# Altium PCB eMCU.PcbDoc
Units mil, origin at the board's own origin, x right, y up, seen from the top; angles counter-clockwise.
Board outline 3031.5 x 2283.46 mil, 2 copper layers (Top Layer, Bottom Layer); 66 components, 80 nets, 347 pads, 50 vias.
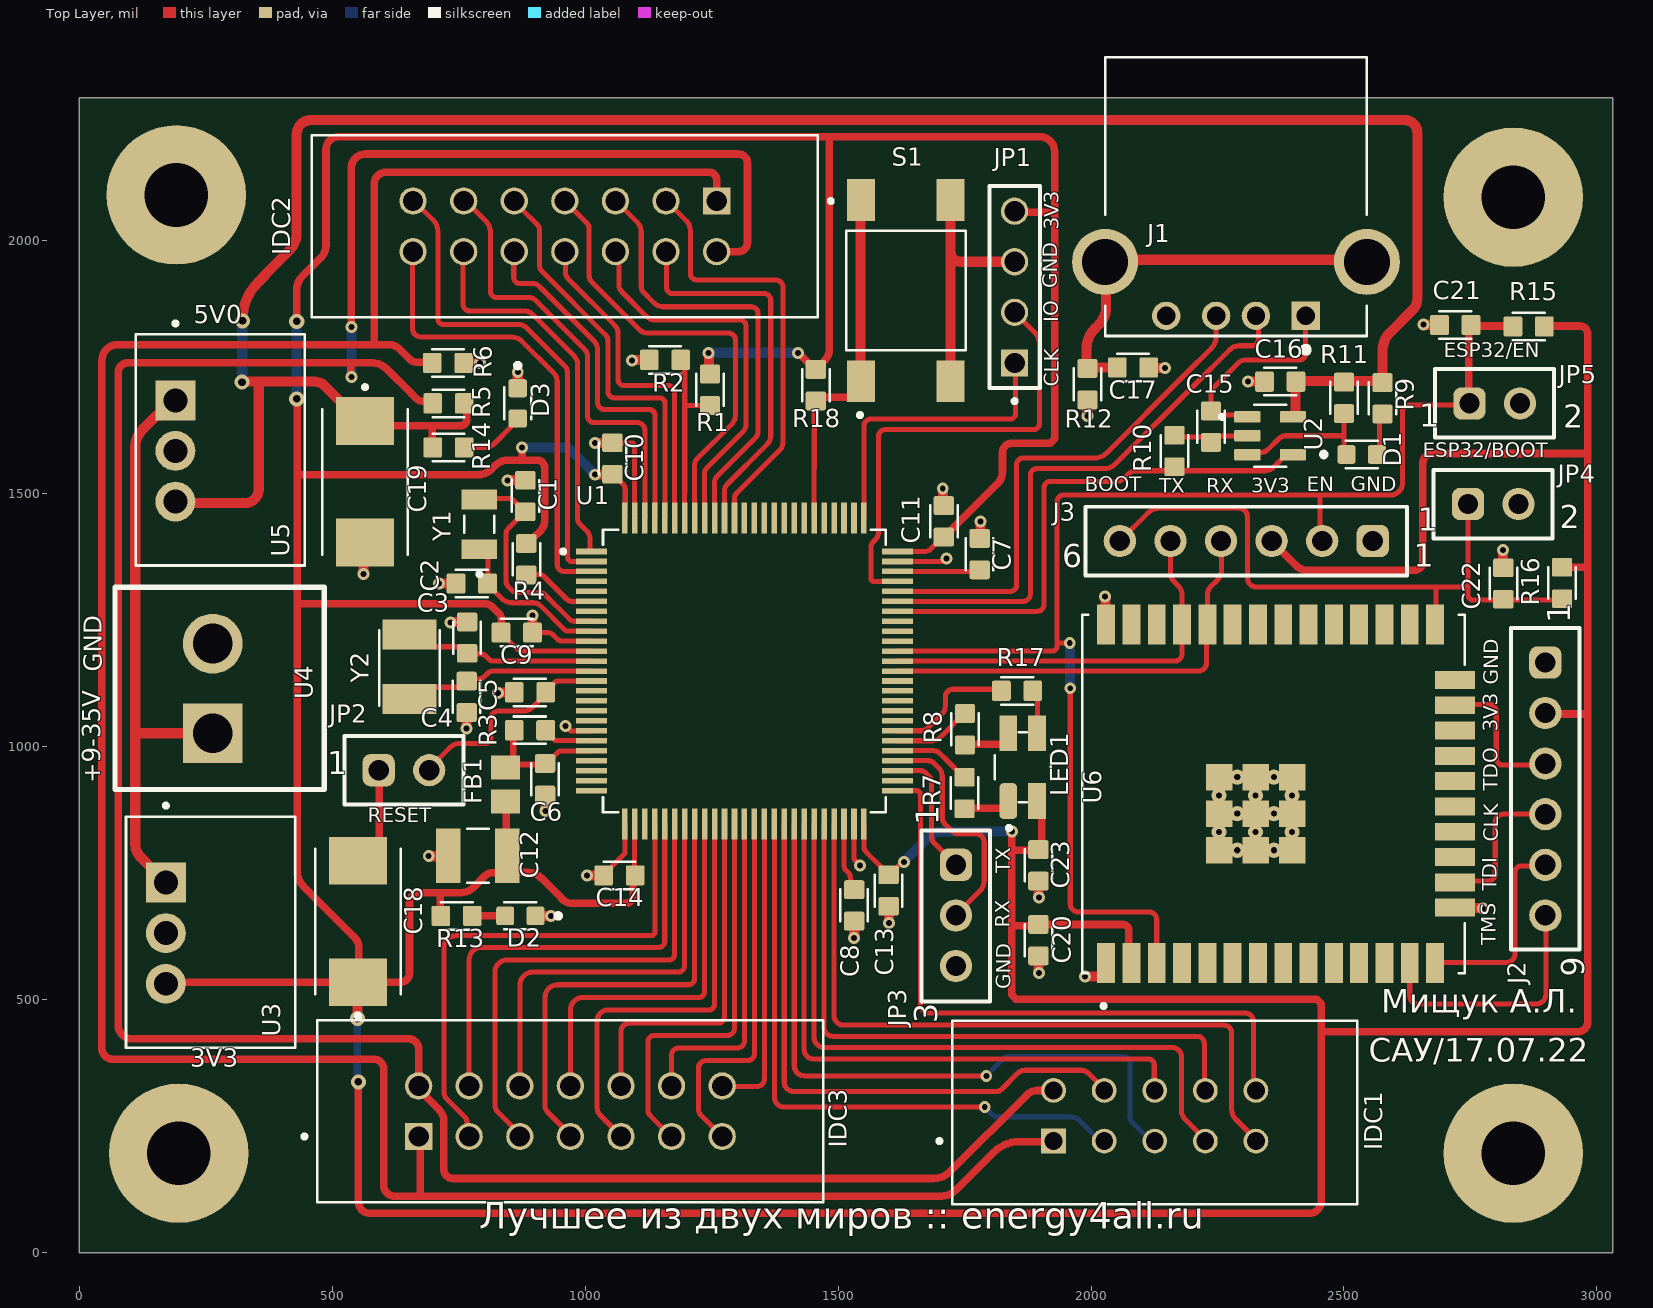
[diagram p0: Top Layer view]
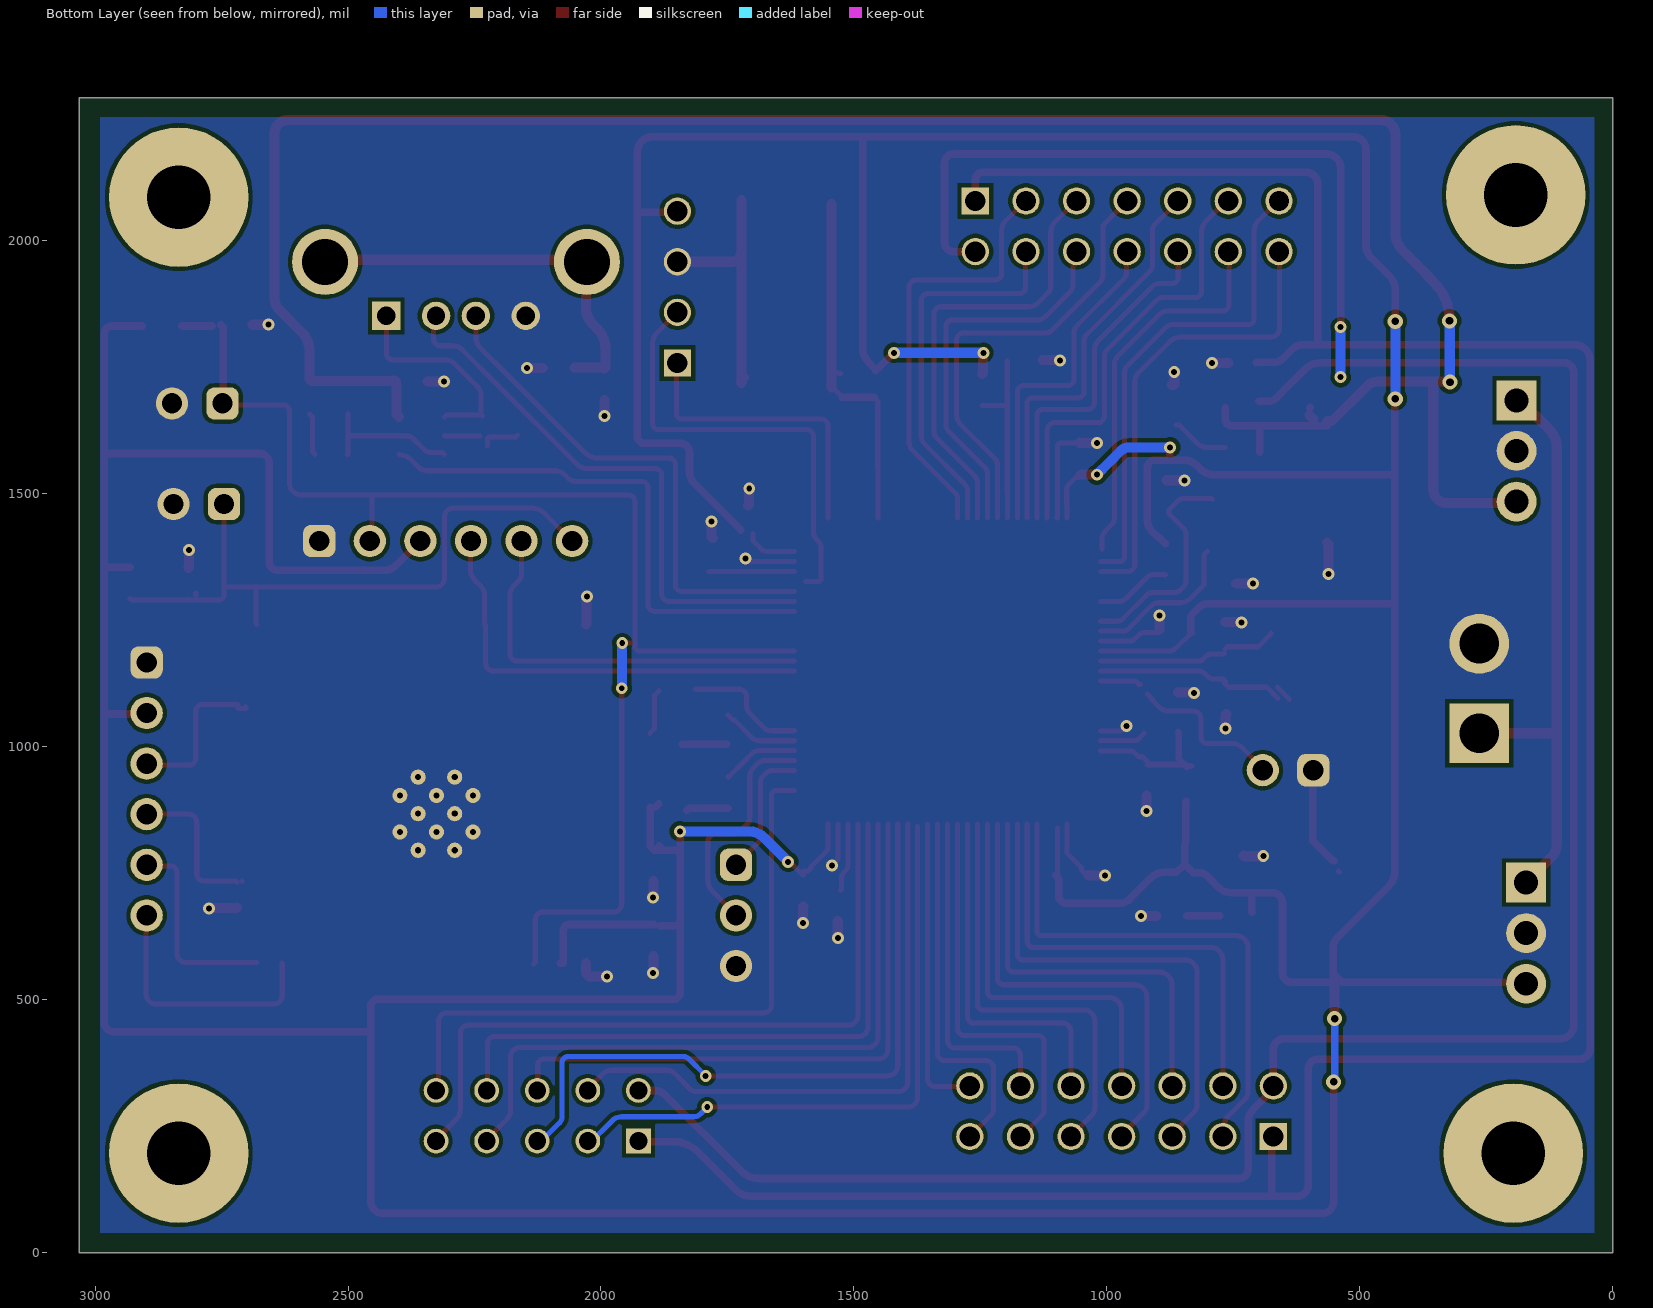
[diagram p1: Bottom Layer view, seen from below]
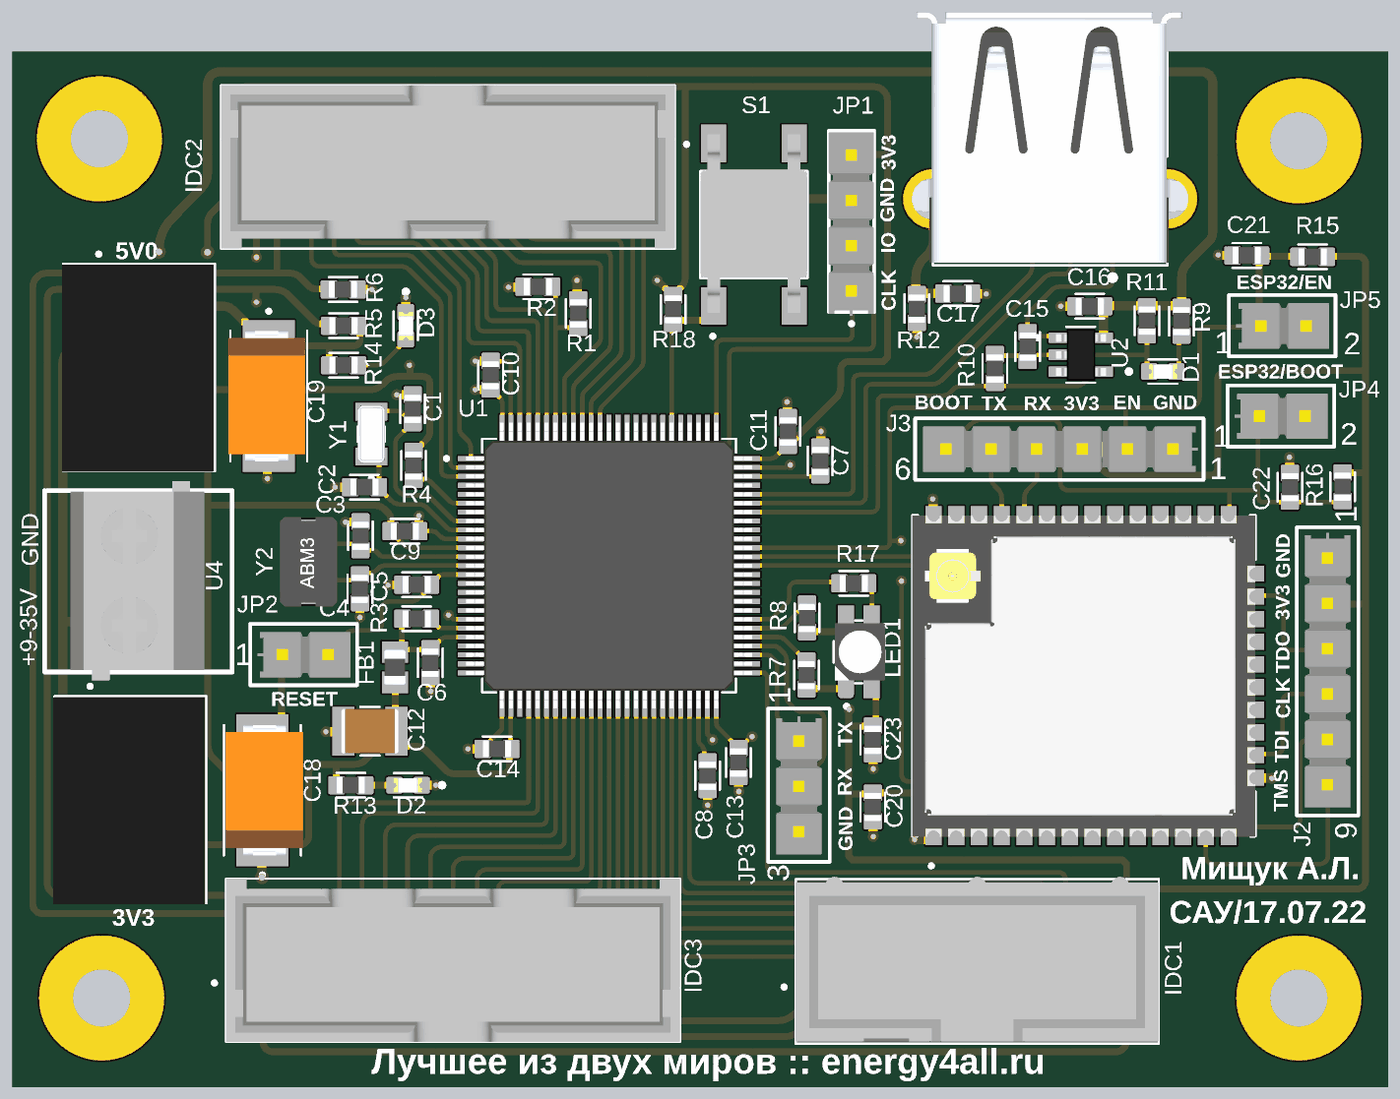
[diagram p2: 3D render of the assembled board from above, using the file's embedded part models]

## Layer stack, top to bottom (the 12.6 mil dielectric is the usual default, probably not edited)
Top Solder: solder mask 0.4, Solder Resist, Dk 3.5
Top Layer: signal copper 1.4
Dielectric 1: dielectric 12.6, FR-4, Dk 4.8
Bottom Layer: signal copper 1.4
Bottom Solder: solder mask 0.4, Solder Resist, Dk 3.5

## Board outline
0,0 3031.5,0 3031.5,2283.46 0,2283.46

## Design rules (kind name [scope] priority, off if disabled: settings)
Clearance [All] p1: gap=7.87 ignorepadtopadclearanceinfootprint=FALSE except(0: Arc-Hole Track-Hole SMDPad-Hole THPad-Hole Via-Hole Fill-Hole Poly-Hole Region-Hole Text-Hole)
HoleSize [All] p1: absolutevalues=TRUE maxlimit=200 minlimit=1 maxpercent=80.000 minpercent=20.000
MinimumSolderMaskSliver [All] p1 off: minsoldermaskwidth=10
PasteMaskExpansion [All] p1 off: expansion=0
PolygonConnect [All] p1: connectstyle=Direct reliefconductorwidth=10 reliefentries=4 polygonreliefangle="90 Angle" airgapwidth=10
RoomDefinition eConnect [InComponentClass('eConnect')] p1: confinementstyle=ConfineOut formatcopy=TRUE lockcomponents=FALSE outline 3083,747 3240,747 3240,817 3083,817
RoomDefinition eMCU [InComponentClass('eMCU')] p2: confinementstyle=ConfineOut formatcopy=TRUE lockcomponents=FALSE outline 3080,827 3240,827 3240,897 3080,897
RoomDefinition eWiFi [InComponentClass('eWiFi')] p3: confinementstyle=ConfineOut formatcopy=TRUE lockcomponents=FALSE outline 3084,520 3241,520 3241,588 3084,588
RoomDefinition eUSB [InComponentClass('eUSB')] p4: confinementstyle=ConfineOut formatcopy=TRUE lockcomponents=FALSE outline 3083,595 3241,595 3241,658 3083,658
RoomDefinition eSupply [InComponentClass('eSupply')] p5: confinementstyle=ConfineOut formatcopy=TRUE lockcomponents=FALSE outline 3082,668 3240,668 3240,738 3082,738
RoutingVias [All] p1: holewidth=28 width=50 viastyle="Through Hole" minholewidth=28 minwidth=50 maxholewidth=28 maxwidth=50
SilkToSilkClearance [All] p1 off: silktosilkclearance=5
SilkToSolderMaskClearance [IsPad] p1 off: minsilkscreentomaskgap=10 clearancetoexposedcopper=TRUE
SolderMaskExpansion [All] p1 off: expansion=4 istentingtop=FALSE
Width [All] p1: maxlimit=50 minlimit=10 preferedwidth=20
25 further rules are at their usual default settings.

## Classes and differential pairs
component class eWiFi: C20 C21 C22 J2 J3 JP4 JP5 R15 R16 U6
component class eUSB: C15 C16 C17 D1 J1 R9 R10 R11 R12 U2
component class eConnect: IDC2 IDC3 R5 R6
component class eSupply: C6 C7 C8 C9 C10 C11 C12 C13 C14 C18 C19 D2 D3 FB1 R3 R4 R13 R14 U3 U4 U5
component class eMCU: C1 C2 C3 C4 C5 C23 IDC1 JP1 JP2 JP3 LED1 R1 R2 R7 R8 R17 R18 S1 U1 Y Y1 Y2

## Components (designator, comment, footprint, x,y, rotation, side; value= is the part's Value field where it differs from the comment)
C1 "22pF" CAP_0603 882,1495.9 r270 top
C2 "22pF" CAP_0603 776,1323 r0 top
C3 "22pF" CAP_0603 767,1216 r270 top
C4 "22pF" CAP_0603 766,1099 r90 top
C5 "0.1uF" CAP_0603 891,1108 r0 top
C6 "0.1uF" CAP_0603 921,936 r90 top
C7 "4.7uF 25V" CAP_0603 1780,1381 r270 top
C8 "4.7uF 25V" CAP_0603 1532,686.9 r90 top
C9 "0.1uF" CAP_0603 865,1226 r180 top
C10 "0.1uF" CAP_0603 1054,1570 r270 top
C11 "0.1uF" CAP_0603 1709,1446 r270 top
C12 "47uF" CAP_1210 788,785 r0 top
C13 "0.1uF" CAP_0603 1600,716 r90 top
C14 "0.1uF" CAP_0603 1068,746 r0 top
C15 "0.1uF" CAP_0603 2237,1633 r270 top
C16 "0.1uF" CAP_0603 2374,1722 r180 top
C17 "0.01uF" CAP_0603 2083,1750 r180 top
C18 "100uF" CAP_TYPE_D 551,655 r90 top
C19 "100uF" CAP_TYPE_D 565,1524 r270 top
C20 "0.1uF" CAP_0603 1896,618 r90 top
C21 "0.1uF" CAP_0603 2720,1834 r0 top
C22 "0.1uF" CAP_0603 2815,1323 r270 top
C23 "0.1uF" CAP_0603 1896,766 r90 top
D1 "led_0603" led_0603 2535,1578 r0 top
D2 "led_0603" led_0603 872,666 r180 top
D3 "led_0603" led_0603 867,1679 r270 top
FB1 "LI0805H151R-10" LI0805H151R-10 843,926 r90 top
IDC1 "IDC-10" IDC-10 1926,221 r0 top
IDC2 "IDC-14" IDC-14 1260,2079 r0 top
IDC3 "IDC-14" IDC-14 671,230 r180 top
J1 "292303-1" TE_292303-1 2424.43,1852 r180 top
J2 "UART" TSW-106-07-F-S 2898,917 r270 top
J3 "UART" TSW-106-07-F-S 2307,1407 r180 top
JP1 "ST-LINK" TSW-104-07-F-S 1849,1759 r90 top
JP2 "RESET" TSW-102-07-F-S 642,954 r0 top
JP3 "TSW-103-07-F-S" TSW-103-07-F-S 1733,667 r270 top
JP4 "RESET" TSW-102-07-F-S 2795,1480 r0 top
JP5 "RESET" TSW-102-07-F-S 2798,1679 r0 top
LED1 "SX-3528-RGB-ANODE" SX-3528-RGB-ANODE 1865,960 r270 top
R1 "DNP" RESC1608X50N 1247,1706 r90 top
R2 "10k" RESC1608X50N 1158,1765 r0 top
R3 "1k" RESC1608X50N 890.9,1033 r0 top
R4 "1k" RESC1608X50N 884,1371 r270 top
R5 "0R" RESC1608X50N 730,1679 r180 top
R6 "0R" RESC1608X50N 729,1759 r180 top
R7 "10K" RESC1608X50N 1750,909 r270 top
R8 "10K" RESC1608X50N 1751,1035 r270 top
R9 "10k" RESC1608X50N 2576,1689 r90 top
R10 "10k" RESC1608X50N 2165,1585 r270 top
R11 "100k" RESC1608X50N 2500,1690 r90 top
R12 "1MOM" RESC1608X50N 1993,1717 r270 top
R13 "10K" RESC1608X50N 746,666 r180 top
R14 "10K" RESC1608X50N 730,1592 r180 top
R15 "10K" RESC1608X50N 2865,1831 r0 top
R16 "10K" RESC1608X50N 2931,1324 r90 top
R17 "10K" RESC1608X50N 1854,1111 r0 top
R18 "10K" RESC1608X50N 1456,1715 r90 top
S1 "2-1437565-8" 2-1437565-8 1634,1902 r90 top
U1 "STM32H750VBT6" STM32H750VBT6 1315,1150 r0 top
U2 "STMPS2151STR" STMPS2151STR 2354,1615 r0 top
U3 "R-78E5.0-1.0" R-78E5.0-1.0 260,632 r270 top
U4 "DG129-5.0-02P" DG129-5.0-02P 264,1115.58 r90 top
U5 "R-78E5.0-1.0" R-78E5.0-1.0 279,1585 r270 top
U6 "ESP32-WROOM-32U" ESP32-WROOM-32U 2361.07,907.37 r90 top
Y1 "32.768K" NX3215SA 791,1440 r90 top
Y2 "8MHZ" NX3225GD 653,1156 r90 top

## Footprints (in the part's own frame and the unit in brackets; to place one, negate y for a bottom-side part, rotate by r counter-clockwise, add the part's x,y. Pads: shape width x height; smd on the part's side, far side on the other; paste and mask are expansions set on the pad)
2-1437565-8 [mm]
  rect 2.1x1.4 smd: 1(-4.55,2.25) 2(4.55,2.25) 3(-4.55,-2.25) 4(4.55,-2.25)
  silkscreen extent -6.35,-3 3,3, body extent -4.95,-3 5.05,3, height 4.28
CAP_0603 [mm]
  rrect20% 0.94x1.02 smd: 1(-0.79,0) 2(0.79,0)
  silkscreen extent -0.8,-0.69 0.8,0.69, body extent -0.8,-0.47 0.8,0.48, height 0.78
CAP_1210 [mm]
  rect 1.24x2.73 smd: 1(-1.485,0) 2(1.485,0)
  silkscreen extent -0.54,-1.36 0.54,1.36, body extent -1.6,-1.25 1.6,1.25, height 1.97
CAP_TYPE_D [mm]
  rect 2.4x2.9 smd: 1(-3.05,0) 2(3.05,0)
  silkscreen extent -4.85,-2.15 3.65,2.15, body extent -3.65,-2.27 3.65,2.03, height 3.1
DG129-5.0-02P [mm]
  rect 3x3 hole 2: 1(-2.25,0)
  round 3 hole 2: 2(2.25,0)
  silkscreen extent -5.08,-5.6 5.08,4.9, body extent -5.55,-4.05 5.61,3.45, height 10.08
ESP32-WROOM-32U [mm]
  rect 2x0.9 smd: 1(-8.5,8.41) 2(-8.5,7.14) 3(-8.5,5.87) 4(-8.5,4.6) 5(-8.5,3.33) 6(-8.5,2.06) 7(-8.5,0.79) 8(-8.5,-0.48) 9(-8.5,-1.75) 10(-8.5,-3.02) 11(-8.5,-4.29) 12(-8.5,-5.56) 13(-8.5,-6.83) 14(-8.5,-8.1) 25(8.5,-8.1) 26(8.5,-6.83) 27(8.5,-5.56) 28(8.5,-4.29) 29(8.5,-3.02) 30(8.5,-1.75) 31(8.5,-0.48) 32(8.5,0.79) 33(8.5,2.06) 34(8.5,3.33) 35(8.5,4.6) 36(8.5,5.87) 37(8.5,7.14) 38(8.5,8.41)
  rect 0.9x2 smd: 15(-5.715,-9.1) 16(-4.445,-9.1) 17(-3.175,-9.1) 18(-1.905,-9.1) 19(-0.635,-9.1) 20(0.635,-9.1) 21(1.905,-9.1) 22(3.175,-9.1) 23(4.445,-9.1) 24(5.715,-9.1)
  rect 1.33x1.33 smd: G.1(0.835,2.745) G.2(-1,2.745) G.4(-2.835,2.745) G.5(0.835,0.91) G.6(-1,0.91) G.7(-2.835,0.91) G.8(0.835,-0.925) G.9(-1,-0.925) G.10(-2.835,-0.925)
  round 0.762 hole 0.305: G.11(-0.082,2.745) G.12(-1.917,2.745) G.13(0.835,1.827) G.14(-1,1.827) G.15(-2.835,1.827) G.16(-0.082,0.91) G.17(-1.917,0.91) G.18(0.835,-0.008) G.19(-1,-0.008) G.20(-2.835,-0.008) G.21(-0.082,-0.925) G.22(-1.917,-0.925)
  silkscreen extent -10.75,-9.6 9,9.6, body extent -9.02,-9.6 8.98,9.6, height 3.3
IDC-10 [mm]
  rect 1.24x1.24 hole 0.89: 1(0,0)
  round 1.24 hole 0.89: 2(0,2.54) 3(2.54,0) 4(2.54,2.54) 5(5.08,0) 6(5.08,2.54) 7(7.62,0) 8(7.62,2.54) 9(10.16,0) 10(10.16,2.54)
  silkscreen extent -5.83,-3.17 15.24,6.04, body extent -5.08,-3.05 15.24,6.17, height 8.89
IDC-14 [mm]
  rect 1.37x1.37 hole 1.02: 1(0,0)
  round 1.37 hole 1.02: 2(0,-2.54) 3(-2.54,0) 4(-2.54,-2.54) 5(-5.08,0) 6(-5.08,-2.54) 7(-7.62,0) 8(-7.62,-2.54) 9(-10.16,0) 10(-10.16,-2.54) 11(-12.7,0) 12(-12.7,-2.54) 13(-15.24,0) 14(-15.24,-2.54)
  silkscreen extent -20.32,-5.84 5.83,3.3, body extent -20.32,-5.84 5.08,3.3, height 9.25
led_0603 [mm]
  rrect25% 0.91x0.93 smd: A(0.76,0) C(-0.76,0)
  silkscreen extent -2.02,-0.68 0.8,0.68, body extent -0.78,-0.4 0.82,0.4, height 0.65
LI0805H151R-10 [mm]
  rect 1.2x1.45 smd: 1(-0.85,0) 2(0.85,0)
  body extent -1,-0.62 1,0.63, height 1.15
NX3215SA [mm]
  rect 1x1.8 smd: 1(-1.25,0) 2(1.25,0)
  silkscreen extent -2.6,-0.75 0.43,0.75, body extent -1.6,-0.75 1.6,0.75, height 0.9
NX3225GD [mm]
  rect 1.5x2.7 smd: 1(-1.552,0.007) 2(1.686,0.002)
  silkscreen extent -1.91,-1.52 1.91,1.52, body extent -2.43,-1.59 2.57,1.61, height 1.3
R-78E5.0-1.0 [mm]
  rect 2x2 hole 1.2: 1(-2.54,-2.25)
  round 2 hole 1.2: 2(0,-2.25) 3(2.54,-2.25)
  silkscreen extent -6.5,-4.25 5.75,4.25, body extent -5.8,-4.31 5.8,4.19, height 10.41
RESC1608X50N [mm]
  rrect20% 0.94x1.02 smd: 1(-0.79,0) 2(0.79,0)
  silkscreen extent -0.8,-0.69 0.8,0.69, body extent -0.79,-0.48 0.81,0.47, height 0.78
STM32H750VBT6 [mm]
  rrect7% 1.56x0.28 smd: 1(-7.68,6) 2(-7.68,5.5) 3(-7.68,5) 4(-7.68,4.5) 5(-7.68,4) 6(-7.68,3.5) 7(-7.68,3) 8(-7.68,2.5) 9(-7.68,2) 10(-7.68,1.5) 11(-7.68,1) 12(-7.68,0.5) 13(-7.68,0) 14(-7.68,-0.5) 15(-7.68,-1) 16(-7.68,-1.5) 17(-7.68,-2) 18(-7.68,-2.5) 19(-7.68,-3) 20(-7.68,-3.5) 21(-7.68,-4) 22(-7.68,-4.5) 23(-7.68,-5) 24(-7.68,-5.5) 25(-7.68,-6) 51(7.68,-6) 52(7.68,-5.5) 53(7.68,-5) 54(7.68,-4.5) 55(7.68,-4) 56(7.68,-3.5) 57(7.68,-3) 58(7.68,-2.5) 59(7.68,-2) 60(7.68,-1.5) 61(7.68,-1) 62(7.68,-0.5) 63(7.68,0) 64(7.68,0.5) 65(7.68,1) 66(7.68,1.5) 67(7.68,2) 68(7.68,2.5) 69(7.68,3) 70(7.68,3.5) 71(7.68,4) 72(7.68,4.5) 73(7.68,5) 74(7.68,5.5) 75(7.68,6)
  rrect7% 0.28x1.56 smd: 26(-6,-7.68) 27(-5.5,-7.68) 28(-5,-7.68) 29(-4.5,-7.68) 30(-4,-7.68) 31(-3.5,-7.68) 32(-3,-7.68) 33(-2.5,-7.68) 34(-2,-7.68) 35(-1.5,-7.68) 36(-1,-7.68) 37(-0.5,-7.68) 38(0,-7.68) 39(0.5,-7.68) 40(1,-7.68) 41(1.5,-7.68) 42(2,-7.68) 43(2.5,-7.68) 44(3,-7.68) 45(3.5,-7.68) 46(4,-7.68) 47(4.5,-7.68) 48(5,-7.68) 49(5.5,-7.68) 50(6,-7.68) 76(6,7.68) 77(5.5,7.68) 78(5,7.68) 79(4.5,7.68) 80(4,7.68) 81(3.5,7.68) 82(3,7.68) 83(2.5,7.68) 84(2,7.68) 85(1.5,7.68) 86(1,7.68) 87(0.5,7.68) 88(0,7.68) 89(-0.5,7.68) 90(-1,7.68) 91(-1.5,7.68) 92(-2,7.68) 93(-2.5,7.68) 94(-3,7.68) 95(-3.5,7.68) 96(-4,7.68) 97(-4.5,7.68) 98(-5,7.68) 99(-5.5,7.68) 100(-6,7.68)
  silkscreen extent -9.2,-7.1 7.1,7.1, body extent -8,-8 8,8, height 1.49
STMPS2151STR [mm]
  rrect25% 1.32x0.59 smd: 1(-1.145,0.95) 2(-1.145,0) 3(-1.145,-0.95) 4(1.145,-0.95) 5(1.145,0.95)
  silkscreen extent -2.51,-1.57 0.8,1.57, body extent -1.38,-1.46 1.42,1.44, height 1.15
SX-3528-RGB-ANODE [mm]
  rrect50% 1.8x0.9 smd: 1(1.7,-0.725)
  rect 1.8x0.9 smd: 2(-1.7,-0.725) 3(-1.7,0.725) 4(1.7,0.725)
  silkscreen extent -1.75,-1.4 3.15,1.4, body extent -1.75,-1.32 1.75,1.48, height 0.8
TE_292303-1 [mm]
  rect 1.428x1.428 hole 0.92: 1(0,0)
  round 1.428 hole 0.92: 2(2.5,0) 3(4.5,0) 4(7,0)
  round 3.316 hole 2.3: SH1(-3.07,-2.71) SH2(10.07,-2.71)
  silkscreen extent -3.07,-12.99 10.06,1.85, body extent -4.44,-13.15 11.56,0.85, height 7.78
TSW-102-07-F-S [mm]
  rrect50% 1.62x1.62 hole 1.02: 1(-1.27,0)
  round 1.62 hole 1.02: 2(1.27,0)
  silkscreen extent -2.99,-1.72 2.98,1.72, body extent -2.58,-1.28 2.62,1.26, height 8.38
TSW-103-07-F-S [mm]
  rrect50% 1.62x1.62 hole 1.02: 1(-2.54,0)
  round 1.62 hole 1.02: 2(0,0) 3(2.54,0)
  silkscreen extent -4.26,-1.72 4.32,1.72, body extent -3.85,-1.27 3.9,1.27, height 8.38
TSW-104-07-F-S [mm]
  rect 1.37x1.37 hole 1.02: 1(0,0)
  round 1.37 hole 1.02: 2(2.54,0) 3(5.08,0) 4(7.62,0)
  silkscreen extent -2.02,-1.27 8.89,1.27, body extent -1.49,-1.25 8.8,1.29, height 9.27
TSW-106-07-F-S [mm]
  rrect50% 1.62x1.62 hole 1.02: 1(-6.35,0)
  round 1.62 hole 1.02: 2(-3.81,0) 3(-1.27,0) 4(1.27,0) 5(3.81,0) 6(6.35,0)
  silkscreen extent -8.07,-1.72 8.07,1.72, body extent -7.75,-1.27 7.62,1.27, height 8.38

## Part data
C1 C2 C3 C4 C5 C6 C7 C8 C9 C10 C11 C13 C14 C15 C16 C17 C20 C21 C22 C23: library part CAP_0603
C12: library part CAP_1210
C18 C19: library part CAP_TYPE_D, Package=None
D1 D2 D3: "LED Indication - Discrete 3.1V 0603 _1608 Metric_", Package="0603 Lite-On"
FB1: "150 Ohms @ 100MHz 1 Power, Signal Line Ferrite Bead 0805 (2012 Metric) 800mA 150mOhm", Package="0805 Laird"
IDC1: "Header, Pin, Idc, Amp-Latch, 10 Pos, Low Profile, Pcb, Vertical, Blue", Package=None
IDC2 IDC3: "HEADER, PIN, AMP-LATCH, 14 POS, 2.54 X 2.54, VERTICAL, LOW PROFILE, PCB", Package=None
J1: "Conn; Data; USB; Recept; 2.0; 4 Pos; 1 Port; Rt Angle; A Ser; Tin over Copper", Package=None
J2 J3: library part TSW-106-07-F-S
JP1: library part TSW-104-07-F-S, "Connector Header Through Hole 4 position 0.100 (2.54mm)", Package=None
JP2 JP4 JP5: library part TSW-102-07-F-S
LED1: "LED; SMD 3528, PLCC2; RGB; 3.5x2.8mm; 120Â°; RGB;   3.2-3.6V", Package="PLCC-2 Lucky Light"
R1 R2 R3 R4 R5 R6 R7 R8 R9 R10 R11 R12 R13 R14 R15 R16 R17 R18: library part RES_0603, "1% 0.1W", Package=None
S1: Package=None
U1: "ARM Cortex-M7 STM32H7 Microcontroller IC 32-Bit 480MHz 128KB _128K x 8_ FLASH 100-LQFP _14x14_", Package="LQFP-100 STMicroelectronics"
U2: library part STMPS2141STR, "Power Switch/Driver 1:1 N-Channel 500mA SOT-23-5", Package="SOT-23 STMicroelectronics"
U3 U5: "1A DC/DC-Converter SIP3", Package="SIP-3 Recom Power"
U4: "DG129-5.0-02P-14-00A(H)"
U6: "Bluetooth, WiFi 802.11b/g/n, Bluetooth v4.2 +EDR, Class 1, 2 and 3 Transceiver Module 2.4GHz ~ 2.5GHz Antenna Not Included, U.FL Surface Mount", Package="Module Espressif Systems"
Y1: library part NX3215SA-32.768K-STD-MUA-8, "32.768 kHz Â±20ppm Crystal 12.5pF 70 kOhms 2-SMD, No Lead", Package="SMD-2 NDK"
Y2: library part NX3225GD, "8MHz Â±20ppm Crystal 18pF 140 Ohms 2-SMD, No Lead", Package="SMD-2 Abracon"

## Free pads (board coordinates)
  round 275.59 hole 125.98: 1(196.85,196.85) 2(192,2091) 3(2834.65,2086.61) 4(2834.65,196.85)

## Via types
v1: diameter 23.62, hole 11.81, Top Layer to Bottom Layer, tented both sides, 44 vias
v2: diameter 30, hole 15, Top Layer to Bottom Layer, tented both sides, 6 vias

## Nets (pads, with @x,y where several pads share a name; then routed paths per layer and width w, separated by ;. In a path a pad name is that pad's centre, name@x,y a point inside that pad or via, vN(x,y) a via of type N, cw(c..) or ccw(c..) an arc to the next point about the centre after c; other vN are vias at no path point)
3V3: C9.2 C10.2 C11.2 C12.2 C13.2 C14.2 C18.1 C20.2 C23.2 FB1.1 J2.2 J3.3 JP1.4 LED1.4 R1.2 R4.1 R13.2 R15.2 R16.2 R18.2 U1.11 U1.27 U1.50 U1.75 U1.100 U3.3 U6.2 | length 15550.6
  Top Layer w10: C9.2 833.9,1224.43 847.4,1210.92 848.08,1210.92 863.77,1195.23 ; 863.78,1195.22 ccw(c877.28,1208.74) 877.28,1189.64 ; 877.28,1189.57 1012.44,1189.57 U1.11 ; C10.2@1057,1533 1061.47,1533 1074.74,1519.74 ; 1074.75,1519.72 cw(c1063.4,1508.4) 1079.42,1509.03 ; U1.100 1078.78,1477.56 1079.42,1478.2 1079.42,1509.03 ; 1079.43,1508.4 ccw(c1063.4,1508.4) 1079.42,1509.03 ; C14.2@1098,740 U1.27@1098,840 ; R1.2@1246.82,1737.29 R1.2 ; U1.50 1551,847.42 1551,804.07 ccw(c1568.07,804.07) 1556,792 1584.92,763.08 1584.92,760.61 1590.43,755.1 C13.2@1600,755.1 ; C13.2 1601.57,747.1 1627.47,773 v1(1630,773) ; U1.75 1617.58,1386 1670,1386 ccw(c1670,1405.31) 1683.66,1391.66 1693.39,1401.39 1693.92,1401.39 1700,1407.47 C11.2@1700,1422 ; JP1.4@1827,2050 JP1.4@1827,2057
  Top Layer w15: U3.3 174.42,535 535.08,535 C18.1@547,546.92 ; v2(430,1688) 431,1687 431,1283 431,754.38 ccw(c472.97,754.38) 443.29,724.71 529.15,638.85 543.1,624.9 cw(c519.2,601) 553,601 553,546.92 551,544.92 C18.1 634.92,534.92 ccw(c634.92,553) 653,553 653,692 cw(c673,692) 673,712 714,712 ; v2(430,1841) 430,1903.44 cw(c467.56,1903.44) 440.97,1929.97 ; 434,1283 800,1283 cw(c800,1256.44) 818.78,1275.22 829.77,1264.23 cw(c819.51,1254) 834,1254 834,1226.1 C9.2 ; 436.29,1538 788.44,1538 ccw(c788.44,1575.56) 814.97,1548.97 ; 441,1930 478,1967 ccw(c453.86,1991.14) 488,1991.14 488,2181 cw(c513,2181) 513,2206 1899,2206 cw(c1899,2177) 1928,2177 1928,1608.79 1919.21,1600 1843,1600 ccw(c1843,1582) 1825,1582 1825,1544.14 cw(c1790.86,1544.14) 1815.02,1520.02 1724.08,1429.08 1724.08,1428.4 C11.2@1723.68,1428 ; C18.1@549,532.92 C18.1@550,531.92 ; v2(552,338) 552,101 ccw(c575,101) 575,78 2431,78 ccw(c2431,102) 2455,102 2455,437 ; R13.2@713,673 ccw(c710.59,675.41) 714,675.41 714,712 ; 815,1549 822.39,1556.39 cw(c848,1530.79) 848,1567 876,1567 ; FB1.1 844,891.54 C12.2@844,811.8 ; C12.2@846.46,806 C12.2 C12.2@846.46,768.25 ; v1(875,1592) 876,1591 876,1567 ; R4.1@885,1402 896.11,1413.11 897.68,1413.11 913.29,1428.71 ; 913,1429 ccw(c896.1,1445.9) 920,1445.9 920,1552 ccw(c905,1552) 905,1567 876,1567 ; C14.2@1096.1,740 1095,738.9 1095,705 cw(c1081,705) 1093,697.78 1088.22,693 cw(c1081,705) 1081,691 975.02,691 cw(c975.02,720.02) 954.51,699.49 912,742 ccw(c887.86,717.86) 887.86,752 862.72,752 C12.2@846.46,768.25 ; C14.2 C14.2@1101,746 ; v1(1421,1779) 1421.53,1779 R18.2@1457,1743.53 ; R18.2 1457.57,1746.1 1468.58,1757.11 1468.58,1758.68 1473.95,1764.05 ccw(c1452.1,1785.9) 1483,1785.9 1483,2203 ; v1(1844,833) 1843,832 1843,792.32 ; JP1.4@1875.68,2057 1927.14,2057 ; C23.2@1883,803.1 C23.2@1884.54,804.65 ; C20.2@1883.85,646.65 1883.61,646.9 1843,646.9 ; LED1.4@1885.54,888.07 LED1.4@1893,880.61 ; C20.2 2062.9,649.1 cw(c2062.9,637) 2066.89,648.42 cw(c2062.9,637) 2074.32,640.99 cw(c2062.9,637) 2075,637 2075,572.72 U6.2 ; LED1.4@1903,880.61 1903,804.1 C23.2 1894.9,796 1846.68,796 1843,792.32 ; J3.3 2405.1,1358.9 ccw(c2429,1382.8) 2429,1349 2639,1349 ccw(c2639,1366) 2656,1366 2656,1561 cw(c2675,1561) 2675,1580 2982,1580 ; J2.2 2900,1065 2982,1065 ; R15.2@2906.34,1832 2966,1832 cw(c2966,1816) 2982,1816 2982,1580 ; R16.2 2931.1,1355 2982,1355 ; 714,712 754.86,712 ccw(c754.86,746.14) 778.98,721.98 802.22,745.22 cw(c817,730.44) 817,751.34 829.56,751.34 C12.2@846.46,768.25 ; 1843,646.9 1843,509.79 1851.79,501 2446.21,501 2455,492.21 2455,437 ; 1843,646.9 1843,792.32 ; 2455,437 2962,437 ccw(c2962,457) 2982,457 2982,1065 ; 2982,1065 2982,1355 ; 2982,1355 2982,1580
  Top Layer w20: v2(550,463) C18.1@550,531.92 ; v1(1020,1538) 1020.45,1538.45 C10.2@1051.55,1538.45 ; v1(1244,1779) 1244.69,1778.31 1244.69,1739.41 R1.2@1246.82,1737.29
  Bottom Layer w15: v2(550,463) 550,340 v2(552,338)
  Bottom Layer w20: v2(430,1688) v2(430,1841) ; v1(875,1592) 956.1,1592 cw(c956.1,1568.1) 973,1585 994.68,1563.32 994.75,1563.32 1020,1538.07 v1(1020,1538) ; v1(1244,1779) v1(1421,1779) ; v1(1630,773) 1677.45,820.45 cw(c1707.83,790.07) 1706.17,833 ; 1707.83,833.03 ccw(c1707.83,790.07) 1706.17,833 ; v1(1844,833) 1706.17,833
5V: C16.1 C19.1 R5.1 R9.2 R11.2 R14.2 U2.5 U5.3 | length 4487.1
  Top Layer w15: C19.1@565,1635 754,1635 ccw(c754,1647) 766,1647 R5.1@766,1670 ; C19.1@598,1671 C19.1@599.1,1669.9 ; R14.2@698,1583 698,1633
  Top Layer w20: U5.3@188,1482 328,1482 ccw(c328,1509) 355,1509 355,1718.59 ccw(c351.59,1718.59) 354,1721 ; v2(323,1842) 323,1845.58 cw(c423,1845.58) 352.29,1916.29 358.22,1922.22 ; v2@333,1722 465.69,1722 cw(c465.69,1694.69) 485,1714 ; 366,1930 358.22,1922.22 ; 415.86,1981.86 369.92,1935.92 369.85,1935.85 ccw(c450.08,1855.62) 358.22,1922.22 ; 415.88,1981.88 ccw(c381.72,2016) 430,2016 430,2211 cw(c458,2211) 435.87,2228.15 cw(c458,2211) 440.85,2233.13 cw(c458,2211) 458,2239 2620,2239 cw(c2620,2214) 2645,2214 2645,1885.73 cw(c2614.27,1885.73) 2636.02,1864.02 2590.29,1818.29 ; 485.12,1714.12 555.16,1644.08 C19.1 ; C19.1@592,1648 C19.1@600,1656 ; U2.5 2403.92,1657.25 C16.1@2403.92,1714.92 ; C16.1 2406.1,1723 C16.1@2408.55,1723 ; C16.1@2409.84,1724.29 C16.1@2408.55,1723 ; 2590.27,1818.27 ccw(c2623.58,1785) 2576.5,1785 2576.5,1727.5 2572,1723 C16.1@2408.55,1723
  Bottom Layer w20: v2(322,1721) 322.5,1721.5 322.5,1841.5 v2(323,1842)
5V_GND: C15.2 R10.1 U2.2 | length 146.6
  Top Layer w10: R10.1 2168.1,1613 2221.92,1613 2224,1610.92 C15.2@2224,1595 ; C15.2@2239.7,1614.23 2308.15,1614.23 U2.2
GND: C1.1 C2.1 C3.1 C4.1 C5.1 C6.1 C7.1 C8.1 C9.1 C10.1 C11.1 C12.1 C13.1 C14.1 C16.2 C17.1 C18.2 C19.2 C20.1 C21.1 C22.1 C23.1 D2.C D3.C J1.4 J2.1 J3.1 JP1.3 JP2.1 JP3.3 JP4.2 JP5.2 R2.1 R6.1 R12.2 S1.3 S1.4 U1.10 U1.19 U1.26 U1.49 U1.74 U1.99 U3.2 U4.2 U5.2 U6.1 U6.15 U6.38 U6.G.1 U6.G.2 U6.G.4 U6.G.5 U6.G.6 U6.G.7 U6.G.8 U6.G.9 U6.G.10 U6.G.11 U6.G.12 U6.G.13 U6.G.14 U6.G.15 U6.G.16 U6.G.17 U6.G.18 U6.G.19 U6.G.20 U6.G.21 U6.G.22 | length 2432.1
  Top Layer w10: C18.2@540.56,752.82 C18.2@542,754.25 ; C9.1 925,1226 cw(c925,1209.1) 936.94,1221.06 944,1214 ccw(c955.94,1225.94) 955.94,1209.06 U1.10 ; C6.1 C6.1@922,903.9 ; v1(961,1041) 962.04,1041 971.15,1031.89 U1.19 ; C14.1 C14.1@1036.9,747 ; C14.1@1038.4,744.5 1050.4,756.5 1050.4,761.4 1078.78,789.78 U1.26 ; C10.1@1059.32,1600.63 1091.37,1600.63 cw(c1091.37,1594) 1092.19,1600.58 cw(c1091.37,1594) 1097.95,1594.82 cw(c1091.37,1594) 1098,1594 1098,1452.83 U1.99 ; U1.49 1531.54,778.67 1543,767.2 v1(1543,766) ; U1.74 1704.85,1366.54 1710.31,1372 v1(1714,1372) ; C7.1@1779,1413.1 C7.1 ; C17.1 C17.1@2115.1,1749 ; C16.2@2339.79,1722 C16.2@2342.9,1725.11 ; C16.2 C16.2@2344,1722 ; J2.1@2898,1177 J2.1@2900.48,1174.52
  Top Layer w15: C18.2 553.26,775.08 593,814.82 JP2.1@593,937.82
  Top Layer w20: v1(562,1342) 562,1400.92 C19.2 ; v1(691,784) 728.54,784 C12.1 ; v1(711,1323) C2.1 ; v1(734,1246) 734.55,1246.55 766.45,1246.55 C3.1 ; R6.1 v1(792,1759) ; C4.1@764,1064.9 766,1062.9 v1(766,1036) ; v1(828,1107) 828.5,1107.5 859.4,1107.5 C5.1 ; v1(847,1527) C1.1 ; v1(867,1741) 867,1716.83 868.11,1715.72 D3.C@872.26,1715.72 ; v1(896,1260) 896.05,1259.95 896.05,1232.05 C9.1@896.1,1232 ; D2.C v1(933,666) ; v1(922,873) 921.5,873.5 921.5,903.4 C6.1@922,903.9 ; v1(1004,746) 1035.9,746 C14.1@1036.9,747 ; v1(1020,1601) 1020.05,1601.05 1053.95,1601.05 C10.1 ; v1(1093.18,1764) 1093.68,1764.5 1126.4,1764.5 R2.1 ; v1(1532,622) C8.1 ; C13.1 1600.5,684.4 1600.5,652.5 v1(1601,652) ; v1(1707,1511) 1707.69,1510.31 1707.69,1478.41 C11.1 ; S1.3@1717,1730 ccw(c1717,1735.58) S1.3@1722.58,1735.58 ; S1.4 1722.58,1977.42 ; S1.3@1723,1719 cw(c1724.01,1720.01) 1722.58,1720.01 S1.3 1722.58,1977.42 ; C7.1@1779,1413.1 1779.1,1413 1781.31,1415.2 1781.31,1445.31 v1(1782,1446) ; JP1.3 1741,1959 cw(c1741,1977.42) 1722.58,1977.42 ; C20.1 1896.5,586.4 1896.5,553.5 v1(1897,553) ; C23.1 1896.5,734.4 1896.5,702.5 v1(1897,702) ; v1(1988,546) 2022.25,546 2029.97,553.72 U6.1 ; v1(1993,1654) R12.2 ; v1(2028,1297) 2028.69,1296.31 2028.69,1243.29 U6.38 ; C17.1@2115.1,1749 v1(2146,1749) ; v1@2314.1,1722 2339.79,1722 C16.2 ; v1(2657,1835) 2657.5,1834.5 2688.4,1834.5 C21.1 ; U6.15 2720.02,681.69 2774.31,681.69 v1(2775,681) ; v1(2814,1389) 2814.5,1388.5 2814.5,1354.6 C22.1
  other v1: 2310.1,1722
NetC1_2: C1.2 U1.8 Y1.2 | length 452
  Top Layer w10: Y1.2 792.79,1491 847.93,1491 cw(c847.93,1473.93) 860,1486 ; 860.16,1486.16 876.93,1469.4 876.93,1460.4 867.92,1451.39 848.58,1432.05 ccw(c859.63,1421) 844,1421 844,1328.07 ccw(c861.07,1328.07) 849,1316 854.34,1310.66 ccw(c868,1324.31) 868,1305 910,1305 cw(c910,1288.1) 921.94,1300.06 969.75,1252.25 ccw(c979,1261.52) 979,1248.42 U1.8
NetC2_2: C2.2 U1.9 Y1.1 | length 309.4
  Top Layer w10: Y1.1@801.31,1387 808,1380.31 C2.2@808,1323 ; C2.2 807.1,1321.43 835.26,1293.26 ccw(c855.21,1313.21) 855.21,1285 897.22,1285 cw(c897.22,1263.81) 912.21,1278.79 957.5,1233.5 ccw(c969,1245.01) 969,1228.74 U1.9
NetC3_2: C3.2 U1.12 Y2.2 | length 550.5
  Top Layer w10: Y2.2@675.55,1225.38 675.55,1223.53 701.08,1198 761.9,1198 C3.2@767,1192.9 ; C3.2@768,1184.9 768.9,1184 793.34,1184 cw(c793.34,1170.34) 803,1180 809.42,1173.58 ccw(c818.9,1183.05) 817.93,1169.68 ; 818.9,1169.65 cw(c818.9,1183.05) 817.93,1169.68 ; 817.93,1169.69 818.9,1169.69 ; 818.9,1169.69 U1.12 818.9,1169.69
NetC4_2: C4.2 U1.13 Y2.1 | length 409.1
  Top Layer w10: Y2.1@638.72,1093.91 Y2.1@662.81,1118 ; Y2.1@661.72,1095.91 683.81,1118 759.9,1118 C4.2@769,1127.1 ; C4.2@766,1127.1 C4.2@767.57,1127.1 ; C4.2 770.12,1134.22 788.05,1134.22 ccw(c788.05,1153.95) 802,1140 807,1145 cw(c819.07,1132.93) 819.07,1150 U1.13
NetC5_2: C5.2 JP2.2 U1.14 | length 400.1
  Top Layer w10: JP2.2 692,958 732.51,998.51 ; 732.53,998.53 cw(c753,978.03) 753,1007 802,1007 ccw(c802,1019) 814,1019 814,1056 cw(c829,1056) 829,1071 877.61,1071 ccw(c877.61,1098.56) 897.83,1079.83 910.6,1092.6 910.6,1094.92 C5.2@920.1,1104.43 ; C5.2@933.61,1123.08 937.61,1123.08 937.61,1124.46 941.07,1127.93 ; 941,1128 cw(c946.59,1122.41) 941.98,1128.84 cw(c946.59,1122.41) 946.59,1130.32 U1.14
NetC6_2: C6.2 FB1.2 R3.1 U1.21 | length 263.5
  Top Layer w10: C6.2@921,972.1 929.5,980.61 937.61,980.61 945,988 cw(c955.56,977.44) 955.56,992.38 1012.49,992.38 U1.21
  Top Layer w12: FB1.2@833,962.46 843.38,962.46 858,977.09 858,1028.1 R3.1@859.9,1030 ; FB1.2 848.64,965.1 C6.2@920,965.1
NetC7_2: C7.2 U1.73 | length 169.6
  Top Layer w10: U1.73 C7.2@1787,1346.85
NetC8_2: C8.2 U1.48 | length 144.3
  Top Layer w10: U1.48 1511.85,765.67 ccw(c1525.49,765.67) 1514.8,757.2 ; 1515.84,756.03 cw(c1525.49,765.67) 1514.8,757.2 ; 1515.91,756.09 1520.16,751.84 ; 1524.28,741.9 ccw(c1510.23,741.9) 1520.17,751.83 ; 1524.35,741.9 1524.35,718.65 C8.2@1527,716 ; 1514.8,757.2 1520.16,751.84
NetC15_1: C15.1 J1.1 U2.1 | length 409.6
  Top Layer w10: C15.1@2234,1654 C15.1@2235,1655 ; C15.1@2235,1656 2305.32,1656 U2.1 ; C15.1 2237,1695.81 cw(c2259.19,1695.81) 2243.5,1711.5 2290,1758 cw(c2306.9,1741.1) 2306.9,1765 2412,1765 ccw(c2412,1777) 2424,1777 2424,1851.57 J1.1
NetC17_2: C17.2 J1.SH1 J1.SH2 R12.1 | length 799.5
  Top Layer w20: R12.1@1991,1750 C17.2 ; R12.1 1993,1754.61 1991,1756.61 1991,1786.67 cw(c2047.33,1786.67) 2007.48,1826.48 2015,1834 ccw(c1978.79,1870.21) 2030,1870.21 2030,1956.66 J1.SH2 ; J1.SH2@2032.28,1963 2540.98,1963 J1.SH1
NetC21_2: C21.2 J3.2 JP5.1 R15.1 U1.65 U6.3 | length 2739.4
  Top Layer w10: U1.65 1617.87,1189.87 1923.87,1189.87 ccw(c1923.87,1199) 1928.27,1191 ccw(c1923.87,1199) 1931.87,1194.6 ccw(c1923.87,1199) 1933,1199 1933,1205 ; v1(1958,1205) 1933,1205 ; v1(1959,1116) 1959,690 ccw(c1975,690) 1975,674 2114,674 cw(c2114,658) 2130,658 2130,574 U6.3@2133,571 ; U6.3@2130.64,600.24 2130.64,620.25 ; J3.2 2453,1411 2453,1498 ; JP5.1 2745,1676 2628,1676 ccw(c2628,1664) 2616,1664 2616,1522 cw(c2592,1522) 2592,1498 2453,1498 ; 1933,1205 1933,1485 cw(c1946,1485) 1946,1498 2453,1498
  Top Layer w15: C21.2@2747,1829 2747,1680 JP5.1 ; C21.2@2748,1830.9 C21.2 ; C21.2@2768.1,1832 R15.1@2828.9,1832
  Bottom Layer w20: v1(1958,1205) 1958.5,1204.5 1958.5,1116.5 v1(1959,1116)
NetC22_2: C22.2 J3.6 JP4.1 R16.1 U6.25 | length 1303.8
  Top Layer w10: J3.6 2112,1462 cw(c2136.14,1437.86) 2136.14,1472 2292,1472 cw(c2292,1455) 2309,1455 2309,1334 ccw(c2327,1334) 2327,1316 2682,1316 ; U6.25 2682,1244.05 2682,1316 ; 2742,1316 2682,1316 ; JP4.1 2745,1301 ccw(c2756,1301) 2756,1290 C22.2@2815,1290 ; C22.2@2801,1300 C22.2@2801,1304.32 ; C22.2 2816.9,1290 2928.1,1290 R16.1
NetD1_A: D1.A R9.1 | length 84.5
  Top Layer w10: D1.A 2570,1583.08 2570,1651.9 R9.1
NetD1_C: D1.C R11.1 U2.3 | length 284.2
  Top Layer w10: U2.3 2313.64,1582.32 2337,1582.32 ccw(c2337,1599.98) 2349.47,1587.47 ; 2349.49,1587.49 2371.5,1609.5 cw(c2384.78,1596.22) 2384.78,1615 2497,1615 ; R11.1 2500,1579.41 ccw(c2503.41,1579.41) D1.C@2501,1577
NetD2_A: D2.A R13.1 | length 65
  Top Layer w15: R13.1 D2.A
NetD3_A: D3.A R14.1 | length 115
  Top Layer w10: R14.1@766.1,1592 802,1592 ccw(c802,1618.56) 820.78,1599.78 856.69,1635.69 856.69,1636.17 D3.A@863.69,1636.17
NetIDC1_1: IDC1.1 IDC2.1 IDC3.1 R6.2 | length 5403.6
  Top Layer w15: 581,1797 583,1799 583,2111.66 cw(c607.34,2111.66) 607.34,2136 1245,2136 cw(c1245,2121) 1260,2121 IDC2.1@1260,2088 ; 652.55,1767.22 ccw(c670,1784.7) 670,1760 703.9,1760 R6.2@704.9,1759 ; 652.53,1767.24 631.64,1788.13 ccw(c612.27,1764.27) 612.27,1795 581,1795 76,1795 ccw(c76,1764) 45,1764 45,404 ccw(c66,404) 66,383 582,383 cw(c582,363) 602,363 602,134 ccw(c624,134) 624,112 674,112 ; IDC3.1 674,227 674,112 ; IDC1.1 1925,220 1858.61,220 ccw(c1858.61,148.52) 1808.06,199.06 1733,124 cw(c1704.03,152.97) 1704.03,112 674,112
NetIDC1_2: IDC1.2 IDC2.2 IDC3.2 R5.2 | length 5599.4
  Top Layer w15: v1(538,1731) 537,1732 537,1759 ; v1(538,1830) 538,2144 cw(c566,2144) 566,2172 1303,2172 cw(c1303,2154) 1321,2154 1321,1997 cw(c1303,1997) 1303,1979 IDC2.2 ; 665.8,1689.2 657,1698 608,1747 ccw(c579.03,1718.03) 579.03,1759 537,1759 ; 665.83,1689.17 ccw(c680,1703.41) 680,1683.32 R5.2@699.58,1683.32 ; IDC2.2@1263,1992 IDC2.2@1267.5,1996.5 ; 1873.51,312.51 1722,161 cw(c1688.2,194.8) 1688.2,147 739,147 cw(c739,165) 721,165 721,259.57 ccw(c688.57,259.57) 711.5,282.5 671,323 671,402.96 ccw(c650.96,402.96) 650.96,423 104.56,423 cw(c104.56,450.56) 77,450.56 77,1740 cw(c96,1740) 96,1759 537,1759 ; 1873.53,312.53 cw(c1894,292.03) 1894,321 IDC1.2
  Bottom Layer w20: v1(538,1731) v1(538,1830)
NetIDC1_3: IDC1.3 U1.41 | length 1229.6
  Top Layer w10: U1.41@1374.06,843.42 1374.57,842.9 1374.57,307 ccw(c1393.57,307) 1393.57,288 v1(1790,288)
  Bottom Layer w10: v1(1790,288) 1803.5,274.5 ccw(c1816.78,287.78) 1816.78,269 1959,269 cw(c1959,240.03) 1974.49,264.51 IDC1.3@2027,212
NetIDC1_4: IDC1.4 U1.42 | length 1186.4
  Top Layer w10: U1.42 1393.74,337.26 ccw(c1412,337.26) 1412,319 1813.34,319 ccw(c1813.34,332.66) 1823,323 1854.93,354.93 cw(c1869.59,340.27) 1869.59,361 1980,361 cw(c1980,339.27) 1995,355 cw(c1980,339.27) 1995.36,354.64 2026,324 IDC1.4
NetIDC1_5: IDC1.5 U1.43 | length 1364.5
  Top Layer w10: U1.43 1413.43,370 ccw(c1433.43,370) 1433.43,350 v1(1793,350)
  Bottom Layer w10: v1(1793,350) 1827,384 cw(c1836.66,374.34) 1836.66,388 2065,388 cw(c2065,376) 2077,376 2077,269 ccw(c2094.29,269) 2080.74,258.26 ; 2084.8,254.04 2082.06,256.78 cw(c2094.29,269) 2080.74,258.26 ; IDC1.5@2127,212 2084.88,254.12 2080.74,258.26
NetIDC1_6: IDC1.6 U1.44 | length 1206.1
  Top Layer w10: U1.44 1433.11,401.89 ccw(c1452,401.89) 1452,383 2114,383 cw(c2114,372) 2125,372 2125,322 IDC1.6
NetIDC1_7: IDC1.7 U1.45 | length 1354.5
  Top Layer w10: U1.45 1452.8,426.2 ccw(c1473,426.2) 1473,406 2160,406 cw(c2160,387) 2179,387 2179,280.9 ccw(c2202.9,280.9) 2186,264 2226,224 IDC1.7
NetIDC1_8: IDC1.8 U1.46 | length 1265.5
  Top Layer w10: U1.46 1472.48,445.52 ccw(c1490,445.52) 1490,428 2210,428 cw(c2210,414) 2224,414 2224,323 IDC1.8
NetIDC1_9: IDC1.9 U1.47 | length 1416.6
  Top Layer w10: U1.47 1492.17,757.69 1492.17,468.83 ccw(c1511,468.83) 1511,450 2263,450 cw(c2263,435) 2278,435 2278,284 ccw(c2306.97,284) 2286.47,263.53 ; 2286.49,263.51 2326,224 IDC1.9
NetIDC1_10: IDC1.10 U1.51 | length 1285.3
  Top Layer w10: U1.51 1657.14,913.78 1663,907.92 1663,490 ccw(c1679,490) 1679,474 2305,474 cw(c2305,458) 2321,458 IDC1.10@2321,315
NetIDC2_3: IDC2.3 U1.89 | length 847.6
  Top Layer w10: IDC2.3@1167.54,2072.46 1200.22,2039.78 cw(c1181.44,2021) 1208,2021 1208,1936 ccw(c1221,1936) 1221,1923 1377,1923 cw(c1377,1909) 1391,1909 1391,1602.9 cw(c1367.1,1602.9) 1384,1586 1299.98,1501.98 1299.43,1501.43 ; U1.89 1295,1452.68 1295,1490 cw(c1311.96,1490) 1299.43,1501.43 ; 1301.06,1503.09 1299.97,1501.99 ccw(c1311.96,1490) 1299.43,1501.43
NetIDC2_4: IDC2.4 U1.90 | length 763.7
  Top Layer w10: IDC2.4 1161,1978 1161,1908 ccw(c1173,1908) 1173,1896 1354,1896 cw(c1354,1883) 1367,1883 1367,1614.9 cw(c1343.1,1614.9) 1360,1598 1280.5,1518.5 ccw(c1293.01,1505.99) 1275.36,1507.16 ; 1275.32,1503.22 1275.32,1505.99 cw(c1293.01,1505.99) 1275.36,1507.16 ; 1275.36,1505.99 1275.36,1507.16 ; U1.90 1275.36,1452.64 1275.36,1507.16
NetIDC2_5: IDC2.5 U1.91 | length 882.5
  Top Layer w10: IDC2.5 IDC2.5@1064,2083 ; IDC2.5@1069.35,2075.21 1069.35,2070.65 1103.22,2036.78 cw(c1084.44,2018) 1111,2018 1111,1910.07 ccw(c1128.07,1910.07) 1116,1898 1136.93,1877.07 ccw(c1154,1894.14) 1154,1870 1328,1870 cw(c1328,1856) 1342,1856 1342,1624.49 cw(c1321.51,1624.49) 1336,1610 1261.5,1535.5 ccw(c1274.78,1522.22) 1256,1522.22 1256,1452.42 U1.91
NetIDC2_6: IDC2.6 U1.92 | length 747.1
  Top Layer w10: IDC2.6@1066.88,1959 1067.18,1958.7 1067.18,1913.06 ccw(c1087.06,1913.06) 1073,1899 1120.5,1851.5 ccw(c1138.61,1869.61) 1138.61,1844 1306,1844 cw(c1306,1832) 1318,1832 1318,1637.49 cw(c1297.51,1637.49) 1312,1623 1241.39,1552.39 ccw(c1253.79,1540) 1236.26,1540 U1.92
NetIDC2_7: IDC2.7 U1.93 | length 897
  Top Layer w10: IDC2.7 1003.52,2035.47 ; 1003.53,2035.47 cw(c992.93,2024.76) 1008,2024.76 1008,1932.49 ccw(c1028.49,1932.49) 1014,1918 1107,1825 ccw(c1123.9,1841.9) 1123.9,1818 1284,1818 cw(c1284,1805) 1297,1805 1297,1654.9 cw(c1273.1,1654.9) 1290,1638 1221,1569 ccw(c1231.92,1558.08) 1216.53,1559.38 1216.53,1558.08 1216.53,1452.41 U1.93
NetIDC2_8: IDC2.8 U1.95 | length 669.8
  Top Layer w10: IDC2.8 961.11,1977.89 961.11,1937.8 ccw(c977.8,1937.8) 966,1926 1058.5,1833.5 cw(c1042.81,1817.81) 1065,1817.81 1065,1727 ccw(c1078,1727) 1078,1714 1165,1714 cw(c1165,1702) 1177,1702 1177,1452.57 U1.95
NetIDC2_9: IDC2.9 U1.96 | length 784.5
  Top Layer w10: IDC2.9@873.14,2064.86 905.53,2032.47 cw(c894.93,2021.76) 910,2021.76 910,1952.07 ccw(c927.07,1952.07) 910,1952 ccw(c927.07,1952.07) 915,1940 1040.05,1814.95 cw(c1028.1,1803) 1045,1803 1045,1703 ccw(c1058,1703) 1058,1690 1147,1690 cw(c1147,1679) 1158,1679 1158,1452.84 U1.96
NetIDC2_10: IDC2.10 U1.97 | length 708.3
  Top Layer w10: IDC2.10@859,1970 859,1928 ccw(c871,1928) 871,1916 895.51,1916 cw(c895.51,1895.51) 910,1910 1017.5,1802.5 cw(c999.39,1784.39) 1025,1784.39 1025,1680 ccw(c1038,1680) 1038,1667 1127,1667 cw(c1127,1656) 1137.83,1657.9 U1.97
NetIDC2_11: IDC2.11 U1.98 | length 872.1
  Top Layer w10: IDC2.11 764,2079 804,2039 cw(c782.27,2017.27) 813,2017.27 813,1901 ccw(c826,1901) 826,1888 889,1888 cw(c889,1868.69) 902.66,1882.34 999.34,1785.66 cw(c985.69,1772) 1005,1772 1005,1654 ccw(c1018,1654) 1018,1641 1103,1641 cw(c1103,1625.9) 1118.09,1625.9 ; U1.98 1118.15,1625.9
NetIDC2_12: IDC2.12 U1.1 | length 743.1
  Top Layer w10: IDC2.12@761,1961 759,1959 759,1874 ccw(c771,1874) 771,1862 880,1862 cw(c880,1840.27) 895.36,1855.64 977.93,1773.07 cw(c960.86,1756) 985,1756 985,1452.07 ccw(c1002.07,1452.07) 990,1440 1002.93,1427.07 cw(c985.86,1410) 1010,1410 U1.1@1010,1390
NetIDC2_13: IDC2.13 U1.2 | length 976.7
  Top Layer w10: IDC2.13@660.5,2080.5 700,2041 cw(c678.27,2019.27) 709,2019.27 709,1846 ccw(c720,1846) 720,1835 866.69,1835 cw(c866.69,1807.69) 885.99,1827.01 959.34,1753.66 cw(c945.69,1740) 965,1740 965,1376.19 ccw(c974.86,1376.19) 966.62,1370.78 ccw(c974.86,1376.19) 969.45,1367.95 ccw(c974.86,1376.19) 972.85,1366.54 ; 974.86,1366.33 cw(c974.86,1376.19) 972.85,1366.54 ; U1.2 974.86,1366.54 972.85,1366.54
NetIDC2_14: IDC2.14 U1.3 | length 904.9
  Top Layer w10: IDC2.14@659,1959 659,1827 ccw(c676,1827) 676,1810 855.69,1810 cw(c855.69,1782.69) 874.99,1802.01 937.93,1739.07 cw(c920.86,1722) 945,1722 945,1360 ccw(c958,1360) 958,1347 ; 958,1346.85 U1.3
NetIDC3_3: IDC3.3 U1.29 | length 1035.6
  Top Layer w10: IDC3.3@765.82,233.18 766.32,233.68 766.32,259 ccw(c752.62,259) 762.32,268.68 726.66,304.34 cw(c740.31,318) 721,318 721,603 cw(c745,603) 745,627 1130.83,627 ccw(c1130.83,634) 1137.83,634 U1.29
NetIDC3_4: IDC3.4 U1.30 | length 904.9
  Top Layer w10: IDC3.4@771,314 771,580 cw(c795,580) 795,604 1146,604 ccw(c1146,615.52) 1157.52,615.52 U1.30
NetIDC3_5: IDC3.5 U1.31 | length 977.3
  Top Layer w10: IDC3.5 871,235 827,279 cw(c839.07,291.07) 822,291.07 822,555 cw(c846,555) 846,579 1166,579 ccw(c1166,590.13) 1177.13,590.13 1177.13,687.4 1177.2,687.48 U1.31
NetIDC3_6: IDC3.6 U1.32 | length 842.8
  Top Layer w10: IDC3.6@871,314 871,529 cw(c897,529) 897,555 1184,555 ccw(c1184,567.59) 1196.59,567.59 1196.59,847.34 U1.32
NetIDC3_7: IDC3.7 U1.33 | length 917
  Top Layer w10: IDC3.7 971,233 926.66,277.34 cw(c940.31,291) 921,291 921,505 cw(c946,505) 946,530 1204,530 ccw(c1204,542.57) 1216.57,542.57 U1.33
NetIDC3_8: IDC3.8 U1.34 | length 783.3
  Top Layer w10: IDC3.8@971,314 971,480 cw(c996,480) 996,505 1225,505 ccw(c1225,516.26) 1236.26,516.26 U1.34
NetIDC3_9: IDC3.9 U1.35 | length 856
  Top Layer w10: 1031,271 1029.66,272.34 cw(c1043.31,286) 1029.62,272.38 ; IDC3.9 1071,231 1029.62,272.38 ; U1.35 1255.94,491.94 cw(c1244,491.94) 1244,480 1045,480 ccw(c1045,459) 1024,459 1024,286 ccw(c1043.31,286) 1029.62,272.38
NetIDC3_10: IDC3.10 U1.36 | length 727.6
  Top Layer w10: 1071,438 cw(c1087,438) 1071.11,439.88 ; IDC3.10@1071.11,314.11 1071.03,325.79 1071.11,325.87 1071.11,439.88 ; U1.36 1275.63,467 cw(c1262.63,467) 1262.63,454 1087,454 ccw(c1087,438) 1071.11,439.88
NetIDC3_11: IDC3.11 U1.37 | length 796.5
  Top Layer w10: 1128.97,271.03 cw(c1141.07,283.07) 1124,283.07 1124,416 cw(c1138,416) 1138,430 1282,430 ccw(c1282,443.31) 1295.32,443.31 U1.37 ; 1129,271 1170,230 IDC3.11
NetIDC3_12: IDC3.12 U1.38 | length 665.6
  Top Layer w10: IDC3.12@1171,314 1171,391 cw(c1185,391) 1185,405 1301,405 ccw(c1301,419) 1315,419 U1.38
NetIDC3_13: IDC3.13 U1.39 | length 735.1
  Top Layer w10: IDC3.13 1229,272 cw(c1241.07,284.07) 1224,284.07 1224,365 cw(c1239,365) 1239,380 1321,380 ccw(c1321,394) 1335,394 1335,610 1334.68,610.31 U1.39
NetIDC3_14: IDC3.14 U1.40 | length 596.3
  Top Layer w10: IDC3.14 1272,329 1340,329 ccw(c1340,343.37) 1354.37,343.37 U1.40
NetJ1_2: J1.2 U1.70 | length 1116.7
  Top Layer w10: U1.70 1866,1287.8 ccw(c1866,1301.8) 1880,1301.8 1880,1537 cw(c1893,1537) 1893,1550 2026.27,1550 ccw(c2026.27,1580.73) 2047.98,1558.98 2206.5,1717.5 2274,1785 cw(c2293.31,1765.69) 2293.31,1793 2318,1793 ccw(c2318,1806) 2331,1806 2331,1850 J1.2@2329,1852
NetJ1_3: J1.3 U1.71 | length 1028.1
  Top Layer w10: U1.71 1698.94,1307.48 1840.48,1307.48 ccw(c1840.48,1320) 1853,1320 1853,1558 cw(c1866,1558) 1866,1571 2006.86,1571 ccw(c2006.86,1605.14) 2030.98,1580.98 2186,1736 2238,1788 ccw(c2215.64,1810.36) 2238.05,1788.05 ccw(c2215.64,1810.36) 2247.26,1810.36 J1.3
NetJ2_3: J2.3 U6.23 | length 314.6
  Top Layer w10: U6.23@2702.19,1076.14 2717.22,1076.14 2717.22,1084 2787,1084 cw(c2787,1070) 2801,1070 2801,977 ccw(c2814,977) 2814,964 2895,964 J2.3 ; U6.23@2702.19,1078.5 U6.23@2703.06,1079.37
NetJ2_4: J2.4 U6.16 | length 299.1
  Top Layer w10: U6.16@2709.19,734.5 U6.16@2709.32,734.37 ; U6.16 2721.97,735 2785,735 ccw(c2785,749) 2799,749 2799,851 cw(c2815,851) 2815,867 J2.4
NetJ2_5: J2.5 U6.14 | length 399.2
  Top Layer w10: U6.14@2679.97,573.97 2820.97,573.97 ccw(c2820.97,591) 2838,591 2838,752 cw(c2851,752) 2851,765 J2.5@2901,765
NetJ2_6: J2.6 U6.13 | length 501.7
  Top Layer w10: U6.13 2629.97,508 ccw(c2645.97,508) 2645.97,492 2880,492 ccw(c2880,511) 2899,511 J2.6@2899,659
NetJ3_4: J3.4 U1.63 U6.34 | length 871
  Top Layer w10: U1.63 2213,1150 ccw(c2213,1165) 2228,1165 U6.34@2228,1242.02 ; U6.34 2229.97,1301 ; 2230,1301 cw(c2251.73,1301) 2236.36,1316.36 2249,1329 ccw(c2227.27,1350.73) 2258,1350.73 2258,1406 J3.4
NetJ3_5: J3.5 U1.64 U6.35 | length 801.1
  Top Layer w10: U1.64 2165.68,1169.69 ccw(c2165.68,1184) 2180,1184 U6.35 2180,1299 ccw(c2151.03,1299) 2171.51,1319.49 2164,1327 cw(c2180.9,1343.9) 2163.96,1327.04 cw(c2180.9,1343.9) 2157,1343.9 J3.5
NetJP1_1: JP1.1 U1.76 | length 604.9
  Top Layer w10: 1551,1634 cw(c1565,1634) 1551.22,1636.47 cw(c1565,1634) 1565,1648 1840,1648 ccw(c1840,1659) 1851,1659 1851,1757 1848,1757 1848,1759 JP1.1 ; U1.76 1551.22,1636.48 1551.22,1634
NetJP1_2: JP1.2 U1.72 | length 891.3
  Top Layer w10: U1.72@1596,1327 1571,1327 cw(c1571,1333) 1565,1333 1565,1393.93 cw(c1582.07,1393.93) 1570,1406 1574,1410 ccw(c1559.51,1424.49) 1580,1424.49 1580,1614 cw(c1593,1614) 1593,1627 1886,1627 ccw(c1886,1639) 1898,1639 1898,1797.98 ccw(c1868.98,1797.98) 1889.51,1818.49 JP1.2
NetJP3_1: JP3.1 U1.53 | length 262.1
  Top Layer w10: U1.53 1662.98,953.15 cw(c1662.98,938.98) 1672.99,949.01 1679.5,942.5 cw(c1666.22,929.22) 1685,929.22 1685,822.07 ccw(c1702.07,822.07) 1690,810 JP3.1
NetJP3_2: JP3.2 U1.54 | length 459.5
  Top Layer w10: U1.54 1677.57,972.83 cw(c1677.57,955.93) 1689.53,967.88 ; 1689.61,967.96 1699.23,958.34 cw(c1682.9,942) 1706,942 1706,860.59 ccw(c1724.36,860.59) 1710.97,848.03 1725,834 ccw(c1739.49,848.49) 1725.04,833.96 ccw(c1739.49,848.49) 1739.49,828 1773,828 cw(c1773,812) 1789,812 1789,737 cw(c1757.62,737) 1779.82,714.82 1750.07,685.07 1750.07,680.93 JP3.2@1755.34,675.66 ; JP3.2@1716,670 JP3.2@1723.83,662.17
NetLED1_1: LED1.1 R7.2 | length 82.6
  Top Layer w15: R7.2@1749,878.9 1826.1,878.9 LED1.1@1830,875
NetLED1_2: LED1.2 R8.2 | length 87
  Top Layer w15: R8.2@1752,1004.9 LED1.2@1839,1004.9
NetLED1_3: LED1.3 R17.2 | length 91.7
  Top Layer w10: R17.2 1894,1102.1 1894,1036.47 LED1.3@1903.54,1026.93
NetR1_1: R1.1 R2.2 U1.94 | length 361.6
  Top Layer w10: U1.94 1196.89,1503 1197,1503 1197,1673 R2.2@1197,1763 ; 1198,1673 1198,1674.9 R1.1
NetR3_2: R3.2 U1.20 | length 92.6
  Top Layer w10: R3.2@926.43,1027 R3.2@938.57,1014.85 ; U1.20 1012.48,1012.36 944.53,1012.36 cw(c944.53,1020.81) R3.2@939.01,1014.41 ; R3.2@938.56,1014.84 ccw(c944.53,1020.81) R3.2@939.01,1014.41 ; R3.2@938.57,1014.85 R3.2@939.01,1014.41
NetR4_2: R4.2 U1.6 | length 149.5
  Top Layer w10: R4.2 884.88,1340.78 908.46,1340.78 cw(c908.46,1324.46) 920,1336 963.4,1292.6 ccw(c975,1304.2) 975,1287.8 U1.6
NetR7_1: R7.1 U1.55 | length 152.1
  Top Layer w10: U1.55 1688.55,992.52 cw(c1688.55,974.8) 1701.08,987.33 ; 1701.14,987.39 1715.46,973.06 1747.43,941.1 R7.1@1749,941.1
NetR8_1: R8.1 U1.56 | length 155.7
  Top Layer w10: U1.56 1686,1012.2 ccw(c1686,1035.72) 1700.35,1017.09 ; 1702.62,1019.09 cw(c1686,1035.72) 1700.35,1017.09 ; 1702.63,1019.09 1703.26,1019.73 ; R8.1@1749,1063 1739.6,1053.6 1736.86,1053.6 1702.49,1019.23 1700.35,1017.09
NetR10_2: R10.2 U1.69 U2.4 | length 1045
  Top Layer w10: U1.69 1894,1268.11 ccw(c1894,1281.11) 1907,1281.11 1907,1512 cw(c1920,1512) 1920,1525 2050.51,1525 ccw(c2050.51,1545.49) 2065,1531 2073.46,1539.46 cw(c2089,1523.92) 2089,1545.9 2344,1545.9 ccw(c2344,1569.79) 2360.9,1552.9 2376.07,1568.07 cw(c2399.08,1545.05) U2.4
NetR17_1: R17.1 U1.57 | length 246.4
  Top Layer w10: U1.57 1617.47,1032 1663.51,1032 ccw(c1663.51,1052.49) 1678,1038 1706,1066 ccw(c1691.51,1080.49) 1712,1080.49 1712,1099 cw(c1727,1099) 1727,1114 R17.1@1813.39,1114
NetR18_1: R18.1 S1.1 S1.2 U1.81 | length 738.4
  Top Layer w10: U1.81 1452.8,1551 1453,1551 1453,1684 R18.1@1460,1691 ; S1.1@1522.86,1691 1544.58,1712.72 1545.42,1713.56 S1.1 ; S1.1@1526,1738 ccw(c1526,1757.42) 1544.58,1751.79 ccw(c1526,1757.42) S1.1@1545.42,1757.42
  Top Layer w15: R18.1@1460,1691 S1.1@1522.86,1691
  Top Layer w20: S1.1@1544.58,1710.87 1544.58,1712.72 1544.58,1751.79 S1.2@1544.58,2073
NetU6_26: U6.26
NetU6_29: U6.29
VCC_9-36V: U3.1 U4.1 U5.1 | length 1129.6
  Top Layer w20: 120.71,782.71 145,758.42 U3.1@145,756 ; 121,783 cw(c145.14,807.14) 111,807.14 111,1027 ; U5.1 161.05,1655.63 153.63,1655.63 125,1627 ccw(c158.8,1593.2) 111,1593.2 111,1027 ; U4.1 111,1027
pads on no net: U1.4 U1.5 U1.7 U1.15 U1.16 U1.17 U1.18 U1.22 U1.23 U1.24 U1.25 U1.28 U1.52 U1.58 U1.59 U1.60 U1.61 U1.62 U1.66 U1.67 U1.68 U1.77 U1.78 U1.79 U1.80 U1.82 U1.83 U1.84 U1.85 U1.86 U1.87 U1.88 U6.4 U6.5 U6.6 U6.7 U6.8 U6.9 U6.10 U6.11 U6.12 U6.17 U6.18 U6.19 U6.20 U6.21 U6.22 U6.24 U6.27 U6.28 U6.30 U6.31 U6.32 U6.33 U6.36 U6.37

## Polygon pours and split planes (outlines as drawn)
GND on Bottom Layer "1" (solid, pour order 0): 36.62,2244.72 2989.38,2244.72 2989.38,40 36.62,40

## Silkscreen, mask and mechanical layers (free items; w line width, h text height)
Top Overlay:
  text "3V3" at 1946,2022 h50 r90
  text "GND" at 1943,1907 h50 r90
  text "IO" at 1945,1839 h50 r90
  text "5V0" at 227,1826 h60
  text "ESP32/EN" at 2697,1760 h50
  text "CLK" at 1946,1712 h50 r90
  text "ESP32/BOOT" at 2656,1563 h50
  text "BOOT" at 1988,1495 h50
  text "EN" at 2426,1495 h50
  text "GND" at 2513,1495 h50
  text "TX" at 2135,1493 h50
  text "RX" at 2228,1493 h50
  text "3V3" at 2317,1493 h50
  text "GND" at 57,1149 h60 r90
  text "GND" at 2815,1123 h50 r90
  text "3V3" at 2814,1030 h50 r90
  text "+9-35V" at 54,928 h60 r90
  text "TDO" at 2814,913 h50 r90
  text "RESET" at 570,841 h50
  text "CLK" at 2815,813 h50 r90
  text "TX" at 1850,750 h50 r90
  text "TDI" at 2812,716 h50 r90
  text "RX" at 1849,643 h50 r90
  text "TMS" at 2810,608 h50 r90
  text "GND" at 1851,521 h50 r90
  text "Мищук А.Л." at 2574,459 h80
  text "САУ/17.07.22" at 2549,362 h80
  text "3V3" at 220,356 h60
  text "Лучшее из двух миров :: energy4all.ru" at 791,30 h90
Mechanical 2:
  the board outline again, w10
